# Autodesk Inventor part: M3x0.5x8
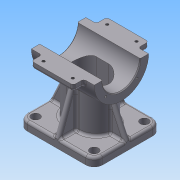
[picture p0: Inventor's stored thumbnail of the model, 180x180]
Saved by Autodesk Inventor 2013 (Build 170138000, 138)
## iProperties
Company: 한국ATC센터
Created: 2009-02
Part Number: M3x0.5x8
Document SubType Name: Modeling
Designer: KYOUNG IL JANG
Density: 2.71 g/cm^3
Material: 알루미늄-6061
Vendor: CBT Solutions
Author: KYOUNG IL JANG
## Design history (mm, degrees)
sketch "스케치1"
  geometry: L1 (-45, 40)-(45, 40); L2 (45, 40)-(45, -40); L3 (45, -40)-(-45, -40); L4 (-45, -40)-(-45, 40); 3 further points
  constraints: 8 end point, 2 midpoint, 2 parallel, 1 horizontal, 1 horizontal alignment, 1 perpendicular, 1 vertical alignment
  dimensions: "d0" = 90 distance of L2.end L3.end; "d1" = 80 distance of L1.end L2.end
extrude "돌출1" new body sketch "스케치1" distance "d2" = 10; taper "d3" = 0 deg
sketch "스케치2"
  geometry: L1 (40, 0)-(-40, 0) reference; C1 r 32.5 at (0, 80); 2 further points
  constraints: 1 centre point, 1 midpoint, 1 vertical alignment
  dimensions: "d4" = 65 diameter of C1; "d5" = 80 distance from line of C1.centre L1
extrude "돌출2" join sketch "스케치2" stored distance "d6" = 75; taper "d7" = 0 deg
sketch "스케치3"
  geometry: L1 (-7.5, -20)-(7.5, -20); L2 (7.5, 20)-(-7.5, 20); A1 r 20 centre (7.5, 0) between (7.5, -20) and (7.5, 20); A2 r 20 centre (-7.5, 0) between (-7.5, 20) and (-7.5, -20); 2 further points
  constraints: 4 end point, 4 point on circle, 4 tangent, 2 centre point, 1 horizontal, 1 horizontal alignment, 1 midpoint, 1 parallel, 1 vertical alignment
  dimensions: "d8" = 20 radius of A2; "d9" = 55 dimension on A1 A2
extrude "돌출3" join sketch "스케치3" stored distance "d10" = 75; taper "d11" = 0 deg
fillet "모깎기1" dims "d12" = 10
sketch "스케치4"
  geometry: L1 (-45, 0)-(-45, 10) reference; L2 (37.5, 47.5)-(-37.5, 47.5) reference; L3 (-45, 10)-(-27.513, 47.5); 1 further point
  constraints: 2 end point, 1 point on line
  dimensions: "d13" = 25 deg angle of L3 L1
sketch "스케치5"
  geometry: L1 (-40, 0)-(-40, 10) reference; L2 (-40, 10)-(-22.912, 56.95); 2 further points
  constraints: 2 end point, 2 other
  dimensions: "d14" = 20 deg angle of L2 L1
feature "리브1" dims "d15" = 1, "d16" = 6, "d17" = 0
feature "리브2" dims "d18" = 1, "d19" = 6, "d20" = 0
fillet "모깎기2" dims "d21" = 3
fillet "모깎기3" dims "d22" = 3
fillet "모깎기4" dims "d23" = 3
fillet "모깎기5" dims "d24" = 3
fillet "모깎기6" dims "d25" = 3
fillet "모깎기7" dims "d26" = 3
fillet "모깎기8" dims "d27" = 3
sketch "스케치6"
  geometry: A1 r 10 centre (35, -30) between (35, -40) and (45, -30) reference; 1 further point
hole "구멍1" sketch "스케치6" at (35, -30) diameter "d28" = 10; stored, may be unused: countersink angle "d32" = 90 deg, drill point angle "d34" = 118 deg; dims "d29" = 6, "d30" = 4, "d31" = 2, "d33" = 8
hole "구멍2" diameter "d37" = 45; stored, may be unused: countersink angle "d41" = 90 deg, drill point angle "d43" = 118 deg; dims "d35" = 10, "d36" = 10, "d38" = 6, "d39" = 4, "d40" = 2, "d42" = 8
sketch "스케치7"
  geometry: C1 r 22.5 at (0, 0) reference; 2 further points
  dimensions: "d44" = 135 deg dimension on C1.centre point (-18.738, 18.738) point (80, 0); "d45" = 26.5 distance of point (-18.738, 18.738) C1.centre
hole "구멍3" sketch "스케치7" at (-18.738, 18.738) diameter "d46" = 2.459; stored, may be unused: countersink angle "d50" = 90 deg, drill point angle "d52" = 118 deg; dims "d47" = 8, "d48" = 4, "d49" = 2, "d51" = 10
node "작업 평면1"
sketch "스케치8"
  geometry: C1 r 10 at (0, 0); 1 further point
  constraints: 1 centre point, 1 coincident
  dimensions: "d57" = 20 diameter of C1
extrude "돌출4" join sketch "스케치8" stored distance "d58" = 75; taper "d59" = 0 deg
hole "구멍4" diameter "d62" = 8.376; stored, may be unused: countersink angle "d66" = 90 deg, drill point angle "d68" = 118 deg; dims "d60" = 10, "d61" = 10, "d63" = 7, "d64" = 4, "d65" = 2, "d67" = 10
chamfer "모따기1" distance "d69" = 1; stored, may be unused: second distance "d70" = 2, angle "d71" = 45 deg
fillet "모깎기9" dims "d72" = 3
sketch "스케치9"
  geometry: L1 (-31.623, 87.5)-(-45, 87.5); L2 (-45, 87.5)-(-45, 72.5); L3 (-45, 72.5)-(-31.623, 72.5); A1 r 32.5 centre (0, 80) between (-31.623, 87.5) and (-31.623, 72.5) reference; 1 further point
  constraints: 6 end point, 2 parallel, 2 point on circle, 1 horizontal, 1 perpendicular
  dimensions: "d73" = 15 distance of L1.end L2.end; "d74" = 45 distance from line of A1.centre L2
extrude "돌출5" join sketch "스케치9" stored distance "d75" = 50; taper "d76" = 0 deg
fillet "모깎기10" dims "d77" = 3
fillet "모깎기11" dims "d78" = 3
sketch "스케치10"
  geometry: L1 (-61.625, 62.366)-(0, 62.366); L2 (0, 62.366)-(0, -62.366); L3 (0, -62.366)-(-61.625, -62.366); L4 (-61.625, -62.366)-(-61.625, 62.366); C1 r 32.5 at (0, 0) reference; 2 further points
  constraints: 8 end point, 2 parallel, 1 coincident, 1 horizontal, 1 midpoint, 1 perpendicular
extrude "돌출6" cut sketch "스케치10" stored distance "d79" = 10; taper "d80" = 0 deg
node "작업 평면2"
sketch "스케치11"
  geometry: L1 (-7.5, -15)-(7.5, -15); L2 (7.5, 15)-(-7.5, 15); A1 r 20 centre (-7.5, 0) between (-7.5, 20) and (-26.807, 5.217) reference; A2 r 20 centre (7.5, 0) between (26.807, 5.217) and (7.5, 20) reference; A3 r 15 centre (7.5, 0) between (7.5, -15) and (7.5, 15); A4 r 15 centre (-7.5, 0) between (-7.5, 15) and (-7.5, -15); 1 further point
  constraints: 4 end point, 4 point on circle, 3 tangent, 2 centre point, 2 coincident, 1 horizontal, 1 parallel
  dimensions: "d82" = 15 radius of A4
extrude "돌출7" cut sketch "스케치11" stored distance "d83" = 10; taper "d84" = 0 deg
sketch "스케치12"
  geometry: 1 further point
hole "구멍5" sketch "스케치12" at (0, 0) diameter "d85" = 12; stored, may be unused: countersink angle "d89" = 90 deg, drill point angle "d91" = 118 deg; dims "d86" = 6, "d87" = 38, "d88" = 10, "d90" = 8
sketch "스케치13"
  geometry: L1 (-15.5, -12.5)-(-59.5, -12.5) reference; 3 further points
  constraints: 1 horizontal alignment
  dimensions: "d92" = 35 distance of point (-20, -5.5) point (-55, -5.5); "d93" = 17.5 horizontal distance of point (-37.5, 32.5) point (-55, -5.5) (= 0.5 x d92); "d94" = 7 distance from line of L1 point (-55, -5.5)
hole "구멍6" sketch "스케치13" at (-55, -5.5), (-20, -5.5) diameter "d95" = 3.242; stored, may be unused: countersink angle "d99" = 90 deg, drill point angle "d101" = 118 deg; dims "d96" = 6, "d97" = 38, "d98" = 10, "d100" = 8
sketch "스케치14"
  geometry: C1 r 10 at (0, 0); 1 further point
  constraints: 1 centre point, 1 coincident
  dimensions: "d102" = 20 diameter of C1
extrude "돌출8" cut sketch "스케치14" distance "d103" = 5; taper "d104" = 0 deg
node "솔리드1"
mirror "대칭1"
mirror "대칭2"
mirror "대칭3"
mirror "대칭4"
pattern_circular "원형 패턴1" dims angle "d54" = 360 deg
mirror "대칭5"
mirror "대칭6"
mirror "대칭7"
other parameters: "d56" = -117
